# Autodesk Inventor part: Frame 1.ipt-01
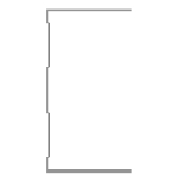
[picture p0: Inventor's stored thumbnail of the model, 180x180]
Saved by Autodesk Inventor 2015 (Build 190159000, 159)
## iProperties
_CCFamilyMember: 1
_CCFamilyDisplayName: Kévin - Kévin Novo
_FrameMemberDoc: Frame Member File
_Version: 15.0.0
_GetPNFromCC: 1
Created: 2015-04
Part Number: Frame 1.ipt-01
Material: Aluminum 6061
Description: Kévin Novo
Document SubType Name: Modeling
Standard: Kevin
Designer: suporte
Standards Organization: Kevin
Language: en-US
Size Designation: (Unnamed 1)
Categories: <MemberInstance><Categories><Category DisplayName="Structural Shapes" InternalName="089c4875-fa83-4c05-b084-43b9cc11f5ed" Mnemonic="GRDR"><CategoryParameter Dis
Density: 2.7 g/cm^3
Appearance: Aluminum - Flat
IsCustomPart: 1
G_L: 475,000 mm
G_W: 50,000 mm
G_H: 75,000 mm
+95B832AB-F253-4C1C-988C-57953EA71A12+CUTDETAIL1: Cut
+17E2C539-7123-446A-946D-B0F1DB25F3F1+CUTDETAIL2: Cut
Author: suporte
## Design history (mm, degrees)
node "Start Plane"
node "End Plane"
sketch "Sketch"
  geometry: L1 (24.7, 37.5)-(24.7, 36.9); L2 (24.7, 36.9)-(-24.7, 36.9); L3 (-24.7, -36.9)-(24.7, -36.9); L4 (24.7, -36.9)-(24.7, -37.5); L5 (24.7, -37.5)-(-25.3, -37.5); L6 (-25.3, 37.5)-(24.7, 37.5); L7 (-24.7, 36.9)-(-24.7, 31.9); L8 (-24.7, 31.9)-(-23.3, 30.5); L9 (-23.3, 30.5)-(-23.3, 10.934); L10 (-23.3, 10.934)-(-24.7, 9.534); L11 (-24.7, 9.534)-(-24.7, -9.534); L12 (-24.7, -9.534)-(-23.3, -10.934); L13 (-23.3, -10.934)-(-23.3, -30.5); L14 (-23.3, -30.5)-(-24.7, -31.9); L15 (-24.7, -31.9)-(-24.7, -36.9); L16 (-25.3, -37.5)-(-25.3, -31.651); L17 (-25.3, -31.651)-(-23.9, -30.251); L18 (-23.9, -30.251)-(-23.9, -11.183); L19 (-23.9, -11.183)-(-25.3, -9.783); L20 (-25.3, -9.783)-(-25.3, 9.783); L21 (-25.3, 9.783)-(-23.9, 11.183); L22 (-23.9, 11.183)-(-23.9, 30.251); L23 (-23.9, 30.251)-(-25.3, 31.651); L24 (-25.3, 31.651)-(-25.3, 37.5); L25 (-25.3, 0)-(30.37, 0); 3 further points
  constraints: 50 end point, 10 point on line, 9 parallel, 5 perpendicular, 4 equal length, 3 midpoint, 3 vertical, 2 vertical alignment, 1 collinear, 1 horizontal, 1 horizontal alignment
  dimensions: "d3" = 0.6 distance of L1.start L1.end (= d6); "d5" = 75 distance between parallel lines of L5 L6; "d6" = 0.6 distance between parallel lines of L24 L7 (= d8); "d7" = 0.6 distance between parallel lines of L8 L23 (= d8); "d8" = 0.6 distance between parallel lines of L22 L9 (= d12); "Espessura" = 0.6 distance between parallel lines of L17 L14; "d10" = 0.6 distance between parallel lines of L13 L18 (= Espessura); "d11" = 0.6 distance between parallel lines of L12 L19 (= Espessura); "d12" = 0.6 distance between parallel lines of L21 L10 (= d11); "d13" = 5 distance of L2.end L7.end; "d15" = 135 deg angle of L9 L8; "d16" = 2 distance between parallel lines of L24 L9; "d17" = 50 distance of L6.start L1.start
extrude "Body" join sketch "Sketch" stored distance "d24" = 0.13; taper "d25" = 0 deg
node "Driven Length"
  sketch "Sketch10"
    geometry: L1 (0, 0)-(10, 0) reference
    constraints: 2 end point, 1 horizontal
  workplane "Work Plane7"
  sketch "Sketch11"
    geometry: L1 (-2, 12.5)-(12, 12.5) reference; L2 (-2, 487.5)-(12, 487.5) reference
    dimensions: "d27" = 475 distance between parallel lines of L1 L2 (derived)
workplane "Work Plane8"
split "Split1"
workplane "Work Plane9"
split "Split2"
body "Solid1"
other parameters: "G_OFFSET_START" = -12.5 [user parameter; used in 1 equation term], "G_OFFSET_END" = -12.5 [user parameter; used in 1 equation term], "d22" = 12.5 (= -G_OFFSET_START), "d23" = 487.5 (= tamanho + G_OFFSET_END), "G_L" = 475 (= d27) [user parameter], "d34" = 90 deg
